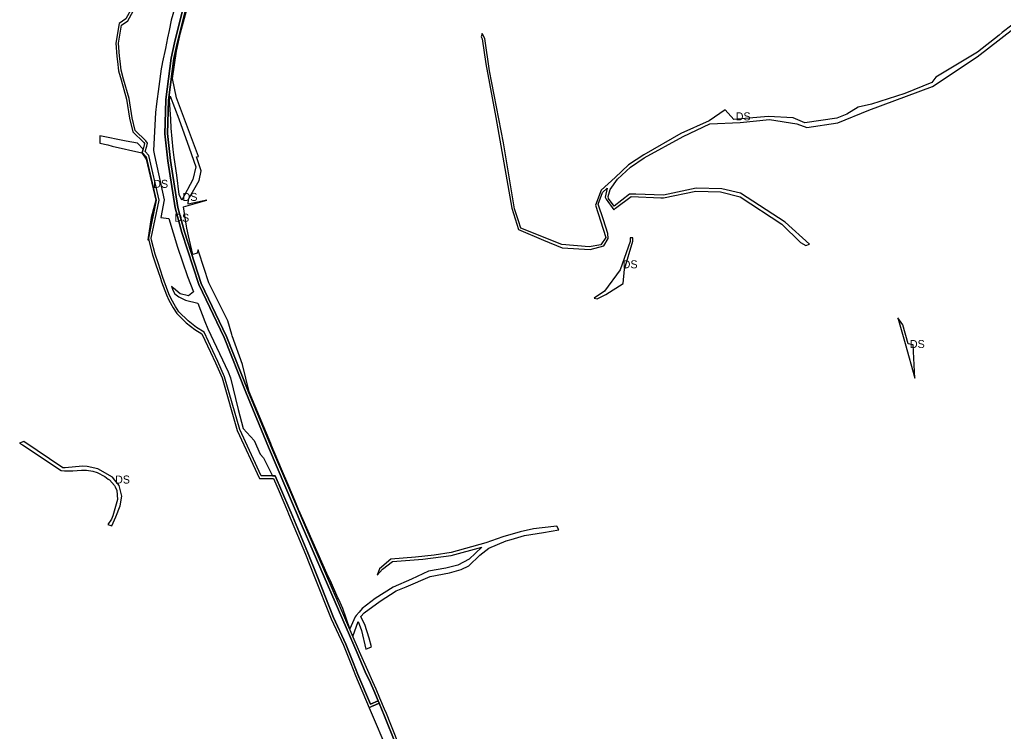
# Model space of a CAD drawing. Extents: x -477304 to -465641, y -1159113 to -1149285.
# Drawn here: x -475673 to -474568, y -1153742 to -1152941 of the extents above; entities that cross this region are included whole.
import ezdxf

# ---------------------------------------------------------------- set-up
doc = ezdxf.new("R2010")
doc.units = 0
for name, color, linetype in [('14', 7, 'Continuous'), ('35', 7, 'Continuous'), ('4', 7, 'Continuous')]:
    doc.layers.add(name, color=color, linetype=linetype)

msp = doc.modelspace()

# ---------------------------------------------------------------- linework, layer by layer
at = {"layer": '14'}
for points in [[(-475375.5, -1152592.4), (-475390.9, -1152636.9), (-475391.9, -1152639.8), (-475391.9, -1152639.8), (-475417.9, -1152715.2), (-475438, -1152776.2), (-475463.1, -1152850.7), (-475489.6, -1152928.1), (-475499.3, -1152967.3), (-475503.1, -1152984.4), (-475509, -1153031.1)], [(-475506, -1153031.7), (-475500.2, -1152984.9), (-475496.4, -1152968), (-475486.7, -1152928.9), (-475460.3, -1152851.7), (-475435.1, -1152777.1), (-475415.1, -1152716.2), (-475389.1, -1152640.8), (-475372.6, -1152593.3)], [(-475509, -1153031.1), (-475509, -1153031.6), (-475510.2, -1153069.5), (-475506.9, -1153100.2), (-475498.7, -1153153), (-475491.2, -1153180.5), (-475472, -1153239.1), (-475443.7, -1153298.7), (-475419.3, -1153360.4), (-475393.8, -1153421.9), (-475355.8, -1153510.9), (-475294.2, -1153653.6), (-475284.9, -1153674.6), (-475279.1, -1153687.3), (-475275.4, -1153695.6), (-475270.4, -1153707.4), (-475269.3, -1153710.1), (-475266, -1153718.1), (-475264, -1153722.7), (-475236.4, -1153791.6)], [(-475233.6, -1153790.5), (-475256, -1153733.9), (-475261.2, -1153721.6), (-475263.2, -1153716.9), (-475268.4, -1153704.4), (-475272.6, -1153694.4), (-475276.3, -1153686.1), (-475282.1, -1153673.4), (-475291.5, -1153652.4), (-475353, -1153509.7), (-475391.1, -1153420.7), (-475416.5, -1153359.2), (-475440.9, -1153297.5), (-475469.3, -1153238), (-475488.3, -1153179.7), (-475495.8, -1153152.4), (-475503.9, -1153099.8), (-475507.2, -1153069.4), (-475506, -1153031.8), (-475506, -1153031.7)]]:
    msp.add_lwpolyline(points, dxfattribs=at)
at = {"layer": '35'}
for p, q in [((-475497.5, -1152922.7), (-475503, -1152941.9)), ((-475503, -1152941.9), (-475505.5, -1152953.3)), ((-475507.2, -1152961.5), (-475509.7, -1152973.6)), ((-475505.5, -1152953.3), (-475507.2, -1152961.5)), ((-475497.2, -1152976.8), (-475494.2, -1152962.8)), ((-475153.3, -1152956.9), (-475154.6, -1152960.7)), ((-475150.5, -1152962.6), (-475153.3, -1152956.9)), ((-475145.1, -1152998.8), (-475150.5, -1152962.6)), ((-474572.3, -1152958.5), (-474596.5, -1152977.8)), ((-474568.7, -1152955.6), (-474572.3, -1152958.5)), ((-475509.7, -1152973.6), (-475512.9, -1152988.7)), ((-475501.5, -1153007.5), (-475497.2, -1152976.8)), ((-474647, -1153016.3), (-474597, -1152983.2)), ((-475514.3, -1152996.5), (-475517.2, -1153016.3)), ((-475513.8, -1152992.9), (-475514.3, -1152996.5)), ((-475512.9, -1152988.7), (-475513.8, -1152992.9)), ((-475497, -1153029.1), (-475501.5, -1153007.5)), ((-475517.2, -1153016.3), (-475519.5, -1153035.8)), ((-475505, -1153031.9), (-475504.3, -1153027.1)), ((-475504.3, -1153027.1), (-475494.6, -1153052.7)), ((-475519.5, -1153035.8), (-475520.6, -1153045.6)), ((-475503.7, -1153053.2), (-475505, -1153031.9)), ((-474715.8, -1153036.2), (-474730.8, -1153039.5)), ((-475138, -1153051.3), (-475120.3, -1153153.2)), ((-474870.5, -1153053.5), (-474880.2, -1153042.7)), ((-475494.6, -1153052.7), (-475482.9, -1153085.4)), ((-474799.6, -1153058.4), (-474788.5, -1153062.6)), ((-474971.3, -1153096.8), (-474927.5, -1153072.7)), ((-475583.2, -1153080.3), (-475574.5, -1153082.2)), ((-475574.5, -1153082.2), (-475569.5, -1153083.4)), ((-475569.5, -1153083.4), (-475536, -1153091)), ((-475541, -1153080.1), (-475553.8, -1153078)), ((-475534.7, -1153087), (-475541, -1153080.1)), ((-475536, -1153091), (-475531.1, -1153098.1)), ((-475535.7, -1153090.5), (-475534.7, -1153087)), ((-475531.1, -1153095.6), (-475535.7, -1153090.5)), ((-475521.8, -1153093.9), (-475511, -1153143.9)), ((-475499.8, -1153096.3), (-475500.9, -1153087.2)), ((-475482.9, -1153085.4), (-475475.6, -1153106.6)), ((-475469.6, -1153111.4), (-475474.5, -1153095.7)), ((-475531.1, -1153098.1), (-475520.3, -1153144.3)), ((-475496.8, -1153116.3), (-475499.8, -1153096.3)), ((-474988.9, -1153104.7), (-475003.9, -1153118.9)), ((-475494, -1153137.9), (-475496.8, -1153116.3)), ((-475471.5, -1153122.3), (-475469.6, -1153111.4)), ((-475491, -1153144.3), (-475494, -1153137.9)), ((-475023, -1153148.9), (-475018.1, -1153135.6)), ((-475018.1, -1153135.6), (-475013, -1153130.9)), ((-475013, -1153130.9), (-475015, -1153140.9)), ((-474987.7, -1153137.7), (-475005.1, -1153150.9)), ((-474980.7, -1153137.4), (-474987.7, -1153137.7)), ((-474949.7, -1153138.8), (-474980.7, -1153137.4)), ((-474949.6, -1153141.7), (-474913.3, -1153134.1)), ((-474913.3, -1153134.1), (-474885.6, -1153134.8)), ((-474885.6, -1153134.8), (-474863.5, -1153140.6)), ((-475511, -1153143.9), (-475514.8, -1153163.7)), ((-475489.4, -1153151.6), (-475478.8, -1153148.8)), ((-475478.8, -1153148.8), (-475463.2, -1153144.4)), ((-475015, -1153140.9), (-475014.1, -1153143.2)), ((-475014.1, -1153143.2), (-475005.6, -1153155)), ((-475005.1, -1153150.9), (-475011.6, -1153142.4)), ((-474863.5, -1153140.6), (-474816.5, -1153171.2)), ((-475120.3, -1153153.2), (-475112.7, -1153177.4)), ((-475112.7, -1153167.4), (-475117.1, -1153153.9)), ((-475005.6, -1153155), (-475003.4, -1153153.3)), ((-475514.8, -1153163.7), (-475505.9, -1153164.8)), ((-475505.9, -1153164.8), (-475496.1, -1153197)), ((-475110.1, -1153175.9), (-475112.7, -1153167.4)), ((-475483.5, -1153184.3), (-475485.5, -1153175.6)), ((-475478.7, -1153205.2), (-475483.5, -1153184.3)), ((-475112.7, -1153177.4), (-475084.4, -1153189.1)), ((-475011.8, -1153187.2), (-475012.3, -1153181.9)), ((-475529.4, -1153188.9), (-475528.4, -1153189)), ((-475014.4, -1153186.1), (-475019.9, -1153194.4)), ((-474993.5, -1153222), (-474983.9, -1153190.3)), ((-474984, -1153186.5), (-474987.2, -1153186.8)), ((-474983.9, -1153190.3), (-474984, -1153186.5)), ((-474789.7, -1153195.2), (-474785.4, -1153193.6)), ((-475473.8, -1153203.7), (-475478.7, -1153205.2)), ((-475472.8, -1153200.2), (-475473.8, -1153203.7)), ((-475472, -1153202.7), (-475472.8, -1153200.2)), ((-475460.8, -1153237.1), (-475472, -1153202.7)), ((-475439.3, -1153280), (-475460.8, -1153237.1)), ((-475501.3, -1153245.6), (-475499, -1153249.8)), ((-475499, -1153249.8), (-475494.5, -1153252.9)), ((-475483.6, -1153251.9), (-475493.2, -1153249.7)), ((-475478.2, -1153247.3), (-475483.6, -1153251.9)), ((-475494.5, -1153252.9), (-475487.2, -1153256.6)), ((-475487.2, -1153256.6), (-475473.3, -1153260.1)), ((-475473.3, -1153260.1), (-475465.2, -1153280.9)), ((-475465.2, -1153280.9), (-475461.8, -1153288.8)), ((-475434.9, -1153295.5), (-475439.3, -1153280)), ((-475461.8, -1153288.8), (-475439.2, -1153337.5)), ((-474674.6, -1153306), (-474680.5, -1153284.5)), ((-475434.6, -1153296.7), (-475434.9, -1153295.5)), ((-475422.8, -1153329), (-475434.6, -1153296.7)), ((-474678, -1153305.4), (-474667, -1153344.6)), ((-474668.8, -1153307.1), (-474674.6, -1153306)), ((-474667, -1153344.6), (-474668.8, -1153307.1)), ((-475439.2, -1153337.5), (-475436.6, -1153344)), ((-475415.4, -1153359.9), (-475422.8, -1153329)), ((-475436.6, -1153344), (-475427.7, -1153379.8)), ((-475403.7, -1153387.6), (-475415.4, -1153359.9)), ((-475427.7, -1153379.8), (-475422.2, -1153401)), ((-475422.2, -1153401), (-475409.7, -1153414.6)), ((-475668.7, -1153415.6), (-475673.5, -1153417.6)), ((-475624.9, -1153445.2), (-475668.7, -1153415.6)), ((-475673.5, -1153417.6), (-475670.4, -1153419.6)), ((-475670.4, -1153419.6), (-475626.8, -1153448.3)), ((-475379.1, -1153446.7), (-475390.5, -1153420.1)), ((-475399.4, -1153433.9), (-475389.4, -1153454.5)), ((-475622.2, -1153445.5), (-475624.9, -1153445.2)), ((-475603, -1153443.6), (-475622.2, -1153445.5)), ((-475613.6, -1153448.6), (-475604, -1153447.8)), ((-475604, -1153447.8), (-475598.5, -1153448)), ((-475370.8, -1153466), (-475379.1, -1153446.7)), ((-475389.4, -1153454.5), (-475386.1, -1153454.5)), ((-475566.7, -1153465.3), (-475566.1, -1153466.8)), ((-475558.7, -1153477.3), (-475560.9, -1153468.3)), ((-475363.8, -1153482.8), (-475370.8, -1153466)), ((-475563.4, -1153480.8), (-475568.8, -1153499.2)), ((-475560.4, -1153488.1), (-475558.7, -1153477.3)), ((-475574.2, -1153508.9), (-475569.8, -1153510.4)), ((-475095.8, -1153514.1), (-475110.6, -1153517.2)), ((-475084.5, -1153518.2), (-475067.1, -1153515)), ((-475067.1, -1153515), (-475069.4, -1153510.8)), ((-475130.2, -1153522.8), (-475149.4, -1153529.7)), ((-475110.6, -1153517.2), (-475130.2, -1153522.8)), ((-475126.4, -1153527.6), (-475120.7, -1153526)), ((-475120.7, -1153526), (-475117.3, -1153525)), ((-475188.3, -1153543.8), (-475153.8, -1153534.5)), ((-475153.8, -1153534.5), (-475168.1, -1153548.2)), ((-475256.2, -1153547.9), (-475268.9, -1153559.1)), ((-475254.4, -1153550.6), (-475220.2, -1153548.1)), ((-475220.2, -1153548.1), (-475188.3, -1153543.8)), ((-475168.1, -1153548.2), (-475181, -1153554.9)), ((-475168.3, -1153555.5), (-475156, -1153543.7)), ((-475268.9, -1153559.1), (-475271.7, -1153566.2)), ((-475271.7, -1153566.2), (-475265.6, -1153559.4)), ((-475265.6, -1153559.4), (-475254.4, -1153550.6)), ((-475177.2, -1153559.5), (-475168.3, -1153555.5)), ((-475233.1, -1153570.7), (-475253.6, -1153579.7)), ((-475213.7, -1153561.7), (-475233.1, -1153570.7)), ((-475250, -1153583.7), (-475242.7, -1153580.7)), ((-475314.6, -1153593.4), (-475315.9, -1153591.6)), ((-475268.3, -1153595.4), (-475250, -1153583.7)), ((-475288.5, -1153603.6), (-475291.9, -1153607.7)), ((-475286.3, -1153608.5), (-475268.3, -1153595.4)), ((-475291.9, -1153607.7), (-475295.1, -1153611.5)), ((-475290, -1153612.5), (-475286.3, -1153608.5)), ((-475287.1, -1153618.2), (-475290, -1153612.5)), ((-475299, -1153635), (-475292.9, -1153618.3)), ((-475292.9, -1153618.3), (-475289, -1153628.4)), ((-475300, -1153632.8), (-475299, -1153635)), ((-475289, -1153628.4), (-475284.4, -1153649.4)), ((-475277.8, -1153646.7), (-475280.4, -1153637.1)), ((-475284.4, -1153649.4), (-475277.8, -1153646.7)), ((-475277.8, -1153713.9), (-475280.6, -1153715.1)), ((-475280.6, -1153715.1), (-475257.5, -1153769.4)), ((-475279, -1153711.1), (-475270.4, -1153707.4)), ((-475273.5, -1153712), (-475277.8, -1153713.9)), ((-475269.3, -1153710.1), (-475273.5, -1153712))]:
    msp.add_line(p, q, dxfattribs=at)
for points in [[(-475509, -1153031.1), (-475503.1, -1152984.4), (-475499.3, -1152967.3), (-475489.6, -1152928.1), (-475463.1, -1152850.7), (-475438, -1152776.2), (-475417.9, -1152715.2), (-475391.9, -1152639.8), (-475391.9, -1152639.8)], [(-475389.1, -1152640.8), (-475415.1, -1152716.2), (-475435.1, -1152777.1), (-475460.3, -1152851.7), (-475486.7, -1152928.9), (-475496.4, -1152968), (-475500.2, -1152984.9), (-475506, -1153031.7)], [(-475494.2, -1152962.8), (-475492.8, -1152956.2), (-475483.8, -1152923), (-475479.4, -1152910), (-475476.9, -1152902.6)], [(-474597, -1152983.2), (-474505.5, -1152911.9), (-474507.8, -1152909.2), (-474536.4, -1152931.1), (-474568.7, -1152955.6)], [(-475154.6, -1152960.7), (-475153.6, -1152962.7), (-475149.4, -1152990.8), (-475138, -1153051.3)], [(-474596.5, -1152977.8), (-474643.3, -1153006), (-474647.8, -1153011.8), (-474678.1, -1153024.3), (-474715.8, -1153036.2)], [(-475117.1, -1153153.9), (-475129.4, -1153079.6), (-475145.1, -1152998.8)], [(-474788.5, -1153062.6), (-474753.6, -1153057.1), (-474718.7, -1153042.9), (-474647, -1153016.3)], [(-475474.5, -1153095.7), (-475472.5, -1153095), (-475497, -1153029.1)], [(-475270.4, -1153707.4), (-475275.4, -1153695.6), (-475279.1, -1153687.3), (-475284.9, -1153674.6), (-475294.2, -1153653.6), (-475355.8, -1153510.9), (-475393.8, -1153421.9), (-475419.3, -1153360.4), (-475443.7, -1153298.7), (-475472, -1153239.1), (-475491.2, -1153180.5), (-475498.7, -1153153), (-475506.9, -1153100.2), (-475510.2, -1153069.5), (-475509, -1153031.6), (-475509, -1153031.1)], [(-475506, -1153031.7), (-475506, -1153031.8), (-475507.2, -1153069.4), (-475503.9, -1153099.8), (-475495.8, -1153152.4), (-475488.3, -1153179.7), (-475469.3, -1153238), (-475440.9, -1153297.5), (-475416.5, -1153359.2), (-475391.1, -1153420.7), (-475353, -1153509.7), (-475300, -1153632.8)], [(-474730.8, -1153039.5), (-474743.4, -1153047.4), (-474754.8, -1153052.1)], [(-475520.6, -1153045.6), (-475523, -1153088.3), (-475521.8, -1153093.9)], [(-474880.2, -1153042.7), (-474898.1, -1153055.2), (-474930.1, -1153069.4), (-474971.8, -1153093.2), (-474988.9, -1153104.7)], [(-474754.8, -1153052.1), (-474790.8, -1153057.2), (-474803.8, -1153051.6), (-474832.1, -1153050.3), (-474870.5, -1153053.5)], [(-475500.9, -1153087.2), (-475503.2, -1153063.1), (-475503.7, -1153053.2)], [(-474927.5, -1153072.7), (-474897.5, -1153058.5), (-474863.4, -1153056.9), (-474830.5, -1153053.6), (-474799.6, -1153058.4)], [(-475553.8, -1153078), (-475583.3, -1153071.9), (-475583.2, -1153080.3)], [(-475528.4, -1153189), (-475528.7, -1153187), (-475519.9, -1153144.4), (-475531.1, -1153095.6)], [(-475475.6, -1153106.6), (-475478.7, -1153120.9), (-475491, -1153144.3)], [(-475011.6, -1153142.4), (-475011.8, -1153140.3), (-475009.4, -1153132.1), (-475001.3, -1153120.6), (-474986.6, -1153107.2), (-474971.3, -1153096.8)], [(-475463.2, -1153144.4), (-475484, -1153148.6), (-475483.5, -1153143.2), (-475471.5, -1153122.3)], [(-475003.9, -1153118.9), (-475019.6, -1153133), (-475025.9, -1153149.9), (-475014.4, -1153186.1)], [(-475003.4, -1153153.3), (-474986.1, -1153140.2), (-474952.5, -1153141.8), (-474949.6, -1153141.7)], [(-474884, -1153131.6), (-474912.8, -1153130.8), (-474949.7, -1153138.8)], [(-474785.4, -1153193.6), (-474812.7, -1153169.1), (-474863, -1153136.3), (-474884, -1153131.6)], [(-475520.3, -1153144.3), (-475525.7, -1153163.7), (-475529.4, -1153188.9)], [(-475012.3, -1153181.9), (-475017, -1153166.2), (-475023, -1153148.9)], [(-475485.5, -1153175.6), (-475485.9, -1153173.5), (-475489.4, -1153151.6)], [(-474816.5, -1153171.2), (-474795.6, -1153191.9), (-474789.7, -1153195.2)], [(-475019.9, -1153194.4), (-475033.3, -1153196.6), (-475063.8, -1153194.3), (-475110.1, -1153175.9)], [(-475084.4, -1153189.1), (-475063.5, -1153197.8), (-475031.9, -1153199.8)], [(-475031.9, -1153199.8), (-475016.8, -1153195.8), (-475011.8, -1153187.2)], [(-474987.2, -1153186.8), (-474987.2, -1153190.9), (-474998.3, -1153222.7)], [(-475496.1, -1153197), (-475484.8, -1153230.1), (-475478.2, -1153247.3)], [(-474998.3, -1153222.7), (-475016, -1153246.6), (-475027.5, -1153254.6), (-475024.1, -1153255.4), (-475014.4, -1153250.5), (-474994.8, -1153237.9), (-474993.5, -1153222)], [(-475493.2, -1153249.7), (-475500.6, -1153243.1), (-475502.8, -1153241.1), (-475501.3, -1153245.6)], [(-474680.5, -1153284.5), (-474686, -1153276.6), (-474678, -1153305.4)], [(-475390.5, -1153420.1), (-475391.1, -1153418), (-475403.7, -1153387.6)], [(-475409.7, -1153414.6), (-475403.1, -1153430.1), (-475399.4, -1153433.9)], [(-475626.8, -1153448.3), (-475623, -1153448.6), (-475613.6, -1153448.6)], [(-475566.4, -1153459.3), (-475569.1, -1153455.8), (-475585.5, -1153446.3), (-475597.7, -1153443.8), (-475603, -1153443.6)], [(-475598.5, -1153448), (-475591.4, -1153449.1), (-475586.5, -1153450.5)], [(-475586.5, -1153450.5), (-475577.9, -1153455.2), (-475573.8, -1153458.2)], [(-475573.8, -1153458.2), (-475572.6, -1153459), (-475566.7, -1153465.3)], [(-475560.9, -1153468.3), (-475561.8, -1153465.1), (-475566.4, -1153459.3)], [(-475386.1, -1153454.5), (-475379.1, -1153470.7), (-475369.8, -1153492.7), (-475368.4, -1153495.9), (-475349.4, -1153541.1), (-475339.5, -1153566), (-475320.5, -1153613.8), (-475306.6, -1153643.7), (-475300, -1153660.4), (-475298.5, -1153664.3), (-475293.2, -1153677.8), (-475279, -1153711.1)], [(-475566.1, -1153466.8), (-475564.2, -1153471), (-475563.4, -1153480.8)], [(-475315.9, -1153591.6), (-475324.1, -1153572.6), (-475328.2, -1153564), (-475354.7, -1153503.9), (-475359.8, -1153492.1), (-475363.8, -1153482.8)], [(-475569.8, -1153510.4), (-475565.4, -1153500.3), (-475560.4, -1153488.1)], [(-475568.8, -1153499.2), (-475570.4, -1153503.2), (-475574.2, -1153508.9)], [(-475069.4, -1153510.8), (-475086.1, -1153512.9), (-475095.8, -1153514.1)], [(-475117.3, -1153525), (-475105.8, -1153521.6), (-475084.5, -1153518.2)], [(-475149.4, -1153529.7), (-475188.3, -1153540.5), (-475207.4, -1153543.6)], [(-475156, -1153543.7), (-475145.8, -1153535.7), (-475126.4, -1153527.6)], [(-475207.4, -1153543.6), (-475228.5, -1153545.7), (-475256.2, -1153547.9)], [(-475181, -1153554.9), (-475194.5, -1153558.2), (-475213.7, -1153561.7)], [(-475212, -1153567.4), (-475190.2, -1153563.4), (-475177.2, -1153559.5)], [(-475242.7, -1153580.7), (-475239.1, -1153579.2), (-475212, -1153567.4)], [(-475253.6, -1153579.7), (-475273.7, -1153592.4), (-475288.5, -1153603.6)], [(-475302.2, -1153626.4), (-475310.2, -1153603.7), (-475314.6, -1153593.4)], [(-475295.1, -1153611.5), (-475296.4, -1153612.9), (-475302.2, -1153626.4)], [(-475280.4, -1153637.1), (-475285.3, -1153621.5), (-475287.1, -1153618.2)], [(-475074.1, -1154119.7), (-475079.5, -1154110.7), (-475125.7, -1154041.5), (-475147.7, -1154000.8), (-475185.4, -1153911.2), (-475187.6, -1153906.2), (-475217, -1153839.7), (-475236.4, -1153791.6), (-475264, -1153722.7), (-475266, -1153718.1), (-475269.3, -1153710.1)]]:
    msp.add_lwpolyline(points, dxfattribs=at)
at = {"layer": '4'}
for p, q in [((-475533, -1153080.7), (-475534.7, -1153087)), ((-475532.4, -1153089.7), (-475530.6, -1153083.5)), ((-475530.6, -1153083.5), (-475529.6, -1153080)), ((-475534.7, -1153087), (-475535.7, -1153090.5)), ((-475535.7, -1153090.5), (-475531.1, -1153095.6)), ((-475528.3, -1153094.2), (-475532.4, -1153089.7)), ((-475505.7, -1153249.5), (-475511.1, -1153235.2)), ((-475503.2, -1153255.3), (-475505.7, -1153249.5)), ((-475498.3, -1153263.7), (-475503.2, -1153255.3)), ((-475494.6, -1153269.8), (-475498.3, -1153263.7)), ((-475450.7, -1153325.9), (-475456.3, -1153313.9)), ((-475386.1, -1153454.5), (-475389.4, -1153454.5)), ((-475388.1, -1153457.5), (-475381.8, -1153471.9)), ((-475381.8, -1153471.9), (-475372.5, -1153493.9)), ((-475372.5, -1153493.9), (-475371.2, -1153497.1)), ((-475323.2, -1153615), (-475309.3, -1153644.9)), ((-475280.6, -1153715.1), (-475277.8, -1153713.9)), ((-475270.4, -1153707.4), (-475279, -1153711.1)), ((-475277.8, -1153713.9), (-475273.5, -1153712))]:
    msp.add_line(p, q, dxfattribs=at)
for points in [[(-475511.7, -1152838), (-475532.9, -1152879.6), (-475536, -1152891.9), (-475539.7, -1152906.9), (-475544.2, -1152922.5), (-475548.4, -1152930.1), (-475554.2, -1152940.4), (-475561.8, -1152945.6), (-475565.3, -1152967.5), (-475564.1, -1152982.6), (-475563.5, -1152988.4), (-475562.4, -1152998.7), (-475559.5, -1153009.1)], [(-475529.6, -1153080), (-475531.8, -1153077.5), (-475543.6, -1153066), (-475547.1, -1153051.6), (-475550.5, -1153030), (-475556.6, -1153008.2), (-475559.4, -1152998.2), (-475560.5, -1152988.1), (-475561.1, -1152982.4), (-475562.3, -1152967.6), (-475559, -1152947.3), (-475551.9, -1152942.4), (-475545.8, -1152931.5)], [(-475559.5, -1153009.1), (-475553.5, -1153030.7), (-475550.1, -1153052.2), (-475546.4, -1153067.5), (-475534, -1153079.5), (-475533, -1153080.7)], [(-475531.1, -1153095.6), (-475519.9, -1153144.4), (-475528.7, -1153187), (-475528.3, -1153189.8), (-475524.1, -1153205.8), (-475520.8, -1153215.7), (-475515.3, -1153232), (-475513.9, -1153236.2), (-475508.5, -1153250.6), (-475505.8, -1153256.7), (-475500.9, -1153265.2), (-475496.9, -1153271.7), (-475486.2, -1153282.2), (-475476.4, -1153289.8), (-475468.6, -1153294.7), (-475459, -1153315.2), (-475453.4, -1153327.2), (-475445.8, -1153344.1), (-475428.9, -1153403.2)], [(-475511.1, -1153235.2), (-475512.5, -1153231.1), (-475517.9, -1153214.8), (-475521.2, -1153204.9), (-475525.3, -1153189.2), (-475525.6, -1153187.1), (-475516.8, -1153144.3), (-475528.3, -1153094.2)], [(-475474.7, -1153287.3), (-475484.2, -1153280), (-475494.6, -1153269.8)], [(-475456.3, -1153313.9), (-475466.2, -1153292.7), (-475474.7, -1153287.3)], [(-475426.1, -1153402.1), (-475443, -1153343), (-475450.7, -1153325.9)], [(-475428.9, -1153403.2), (-475403.9, -1153457.5), (-475388.1, -1153457.5)], [(-475389.4, -1153454.5), (-475401.9, -1153454.5), (-475426.1, -1153402.1)], [(-475279, -1153711.1), (-475293.2, -1153677.8), (-475298.5, -1153664.3), (-475300, -1153660.4), (-475306.6, -1153643.7), (-475320.5, -1153613.8), (-475339.5, -1153566), (-475349.4, -1153541.1), (-475368.4, -1153495.9), (-475369.8, -1153492.7), (-475379.1, -1153470.7), (-475386.1, -1153454.5)], [(-475371.2, -1153497.1), (-475352.2, -1153542.3), (-475342.3, -1153567.1), (-475323.2, -1153615)], [(-475309.3, -1153644.9), (-475302.8, -1153661.5), (-475301.3, -1153665.4)], [(-475301.3, -1153665.4), (-475295.9, -1153678.9), (-475280.6, -1153715.1)], [(-475273.5, -1153712), (-475269.3, -1153710.1), (-475270.4, -1153707.4)]]:
    msp.add_lwpolyline(points, dxfattribs=at)

# ---------------------------------------------------------------- texts
at = {"layer": '35'}
for p in [(-474868.4, -1153054.5), (-475523.3, -1153130.4), (-475490.3, -1153145.1), (-475499.6, -1153168.5), (-474995.5, -1153220.9), (-474672.6, -1153310.6), (-475566.2, -1153463)]:
    msp.add_text('DS', height=9, dxfattribs=at).set_placement(p)

doc.saveas('drawing.dxf')
